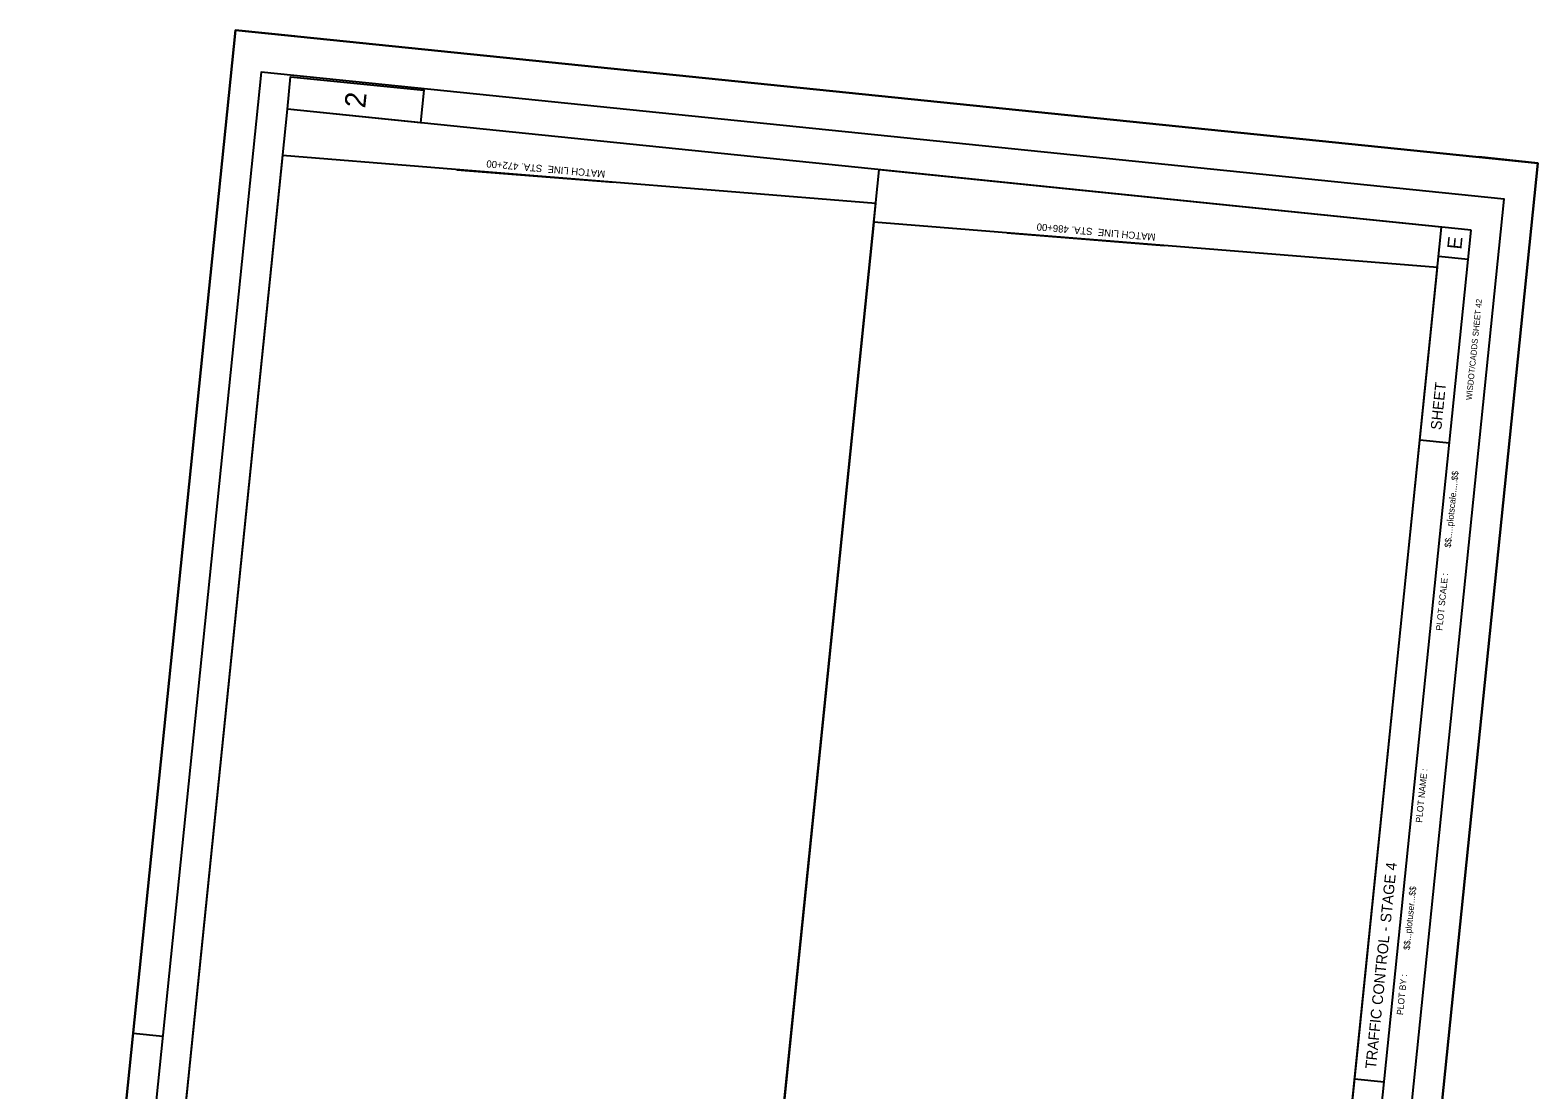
# Model space of a CAD drawing. Extents: x 359453 to 360720, y 169866 to 171669.
# Drawn here: x 359453 to 360720, y 170778 to 171669 of the extents above; entities that cross this region are included whole.
import ezdxf

# ---------------------------------------------------------------- set-up
doc = ezdxf.new("R2010")
doc.units = 0
for name, color, linetype in [('CA-MTCH-LINE', 7, 'Continuous'), ('CA-MTCH-LINE-TEXT', 7, 'Continuous'), ('Default', 7, 'Continuous'), ('P_Kapur_PFFE CELL [KAPUR_CADDS_LEVELS]', 7, 'Continuous'), ('P_RDWY_Text', 7, 'Continuous'), ('P_SHTIDX_2 [KAPUR_CADDS_LEVELS]', 7, 'Continuous'), ('PLT_Sheet_Border', 7, 'Continuous'), ('PLT_Sheet_Info', 7, 'Continuous')]:
    doc.layers.add(name, color=color, linetype=linetype)

msp = doc.modelspace()

# ---------------------------------------------------------------- linework, layer by layer
at = {"layer": 'CA-MTCH-LINE'}
for p, q in [((359812, 171551.3), (359943.8, 171540.7)), ((360274.4, 171498.3), (360406.3, 171487.7))]:
    msp.add_line(p, q, dxfattribs=at)
at = {"layer": 'Default'}
for points in [[(359509.5, 170035.2), (359824.6, 170003.1), (359867.1, 170420.4), (360049.6, 170401.8), (360049.6, 170401.8), (360164, 171523), (359665.5, 171563.1)], [(359509.5, 170035.2), (359824.6, 170003.1), (359867.1, 170420.4), (360049.6, 170401.8), (360164, 171523), (359665.5, 171563.1)], [(359509.5, 170035.2), (359824.6, 170003.1), (359867.1, 170420.4), (360049.6, 170401.8), (360164, 171523), (359665.5, 171563.1)], [(360049.6, 170401.8), (360036.5, 170273.7), (360108.9, 170205), (360088.7, 170008.7), (360483.7, 169976.8), (360636, 171469.2), (360162.4, 171507.3)], [(360049.6, 170401.8), (360036.5, 170273.7), (360108.9, 170205), (360088.7, 170008.7), (360483.7, 169976.8), (360636, 171469.2), (360162.4, 171507.3)], [(360049.6, 170401.8), (360036.5, 170273.7), (360108.9, 170205), (360088.7, 170008.7), (360483.7, 169976.8), (360636, 171469.2), (360162.4, 171507.3)]]:
    msp.add_lwpolyline(points, close=True, dxfattribs=at)
at = {"layer": 'P_Kapur_PFFE CELL [KAPUR_CADDS_LEVELS]'}
msp.add_lwpolyline([(359453.4, 169977.4), (359626, 171668.6), (360720.3, 171556.9), (360547.7, 169865.7), (359453.4, 169977.4)], dxfattribs=at)
at = {"layer": 'P_RDWY_Text'}
msp.add_lwpolyline([(359453.4, 169977.4), (359626, 171668.6), (360720.3, 171556.9), (360547.7, 169865.7)], close=True, dxfattribs=at)
at = {"layer": 'P_SHTIDX_2 [KAPUR_CADDS_LEVELS]'}
msp.add_lwpolyline([(360639.4, 171503.1), (360166.9, 171551.3)], dxfattribs=at)
at = {"layer": 'PLT_Sheet_Border'}
for points in [[(360547.7, 169865.7), (360720.3, 171556.9), (359626, 171668.6), (359453.4, 169977.4)], [(360524, 169880.2), (360692.1, 171526.6), (359647.5, 171633.2), (359479.5, 169986.8)]]:
    msp.add_lwpolyline(points, close=True, dxfattribs=at)
at = {"layer": 'PLT_Sheet_Info'}
for p, q in [((359620.9, 171618.8), (359626, 171668.6)), ((359675.7, 171663.5), (359626, 171668.6)), ((359509.5, 170035.2), (359669.5, 171602.1)), ((360664.3, 171500.5), (359669.5, 171602.1)), ((360720.3, 171556.9), (360670.6, 171562)), ((360715.2, 171507.2), (360720.3, 171556.9)), ((360039.5, 170303.6), (360166.9, 171551.3)), ((360479.5, 169936.2), (360639.4, 171503.1)), ((360504.4, 169933.7), (360664.3, 171500.5)), ((360661.7, 171475.7), (360636.9, 171478.2)), ((360646, 171321.5), (360621.1, 171324)), ((359537.4, 170800.6), (359542.5, 170850.3)), ((359539.9, 170825.5), (359564.8, 170822.9)), ((360591.2, 170784.3), (360566.3, 170786.8))]:
    msp.add_line(p, q, dxfattribs=at)
msp.add_lwpolyline([(359669.5, 171602.1), (359672.2, 171629.4), (359784.2, 171618), (359781.4, 171590.7)], close=True, dxfattribs=at)

# ---------------------------------------------------------------- texts
at = {"layer": 'CA-MTCH-LINE-TEXT'}
for s, p in [('MATCH LINE  STA. 472+00', (359936.8, 171550.5)), ('MATCH LINE  STA. 486+00', (360399.2, 171497.5))]:
    msp.add_text(s, height=6, rotation=174.9815, dxfattribs=at).set_placement(p)
at = {"layer": 'PLT_Sheet_Info'}
for s, height, p in [('2', 17.5, (359734.9, 171602.6)), ('E', 12, (360656, 171483.9)), ('WISDOT/CADDS SHEET 42', 5, (360664.8, 171357.4)), ('SHEET ', 9, (360639.1, 171332.2)), ('$$.....plotscale.....$$', 5.4, (360647.1, 171233.4)), ('PLOT SCALE : ', 5.4, (360640, 171163.6)), ('PLOT NAME :                      ', 5.4, (360623, 171002.2)), ('TRAFFIC CONTROL - STAGE 4', 9, (360584.2, 170795)), ('$$...plotuser...$$', 5.4, (360612.6, 170895.2)), ('PLOT BY :', 5.4, (360607, 170840.5))]:
    msp.add_text(s, height=height, rotation=84.1728, dxfattribs=at).set_placement(p)

doc.saveas('drawing.dxf')
